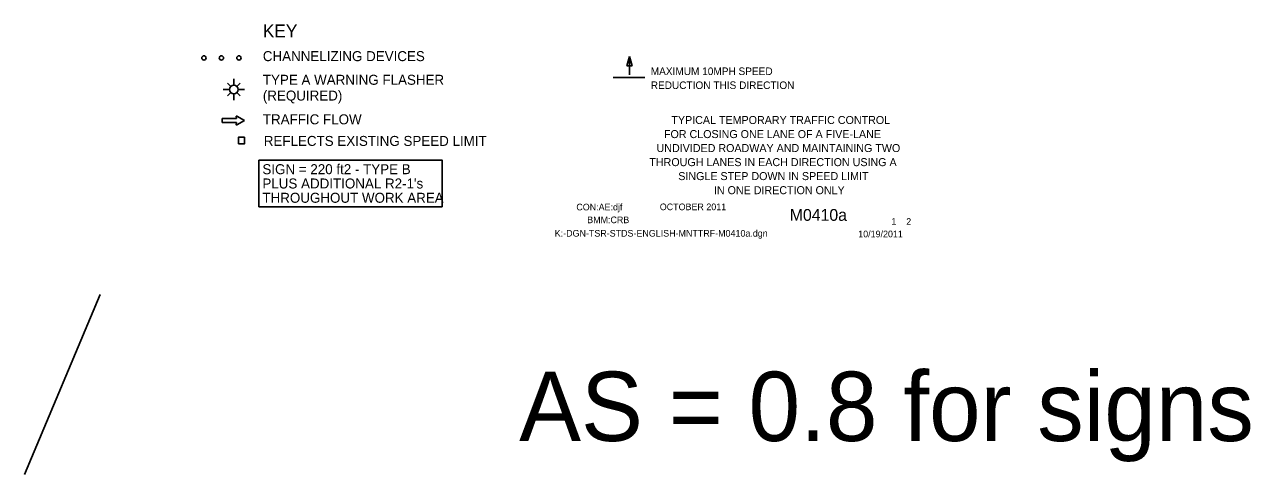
# Model space of a CAD drawing. Extents: x 16577 to 18475, y 5712 to 6919.
# Drawn here: x 16577 to 17718, y 5712 to 6131 of the extents above; entities that cross this region are included whole.
import ezdxf

# ---------------------------------------------------------------- set-up
doc = ezdxf.new("R2010")
doc.units = 0
for name, color, linetype in [('BORDER_SIGNAL_WO', 7, 'Continuous'), ('MT_SCRATCH_LEVEL_E', 7, 'Continuous'), ('TRAFFIC_SIGNS_PR', 7, 'Continuous'), ('TYPICAL_TEXT_DIMEN_EX', 7, 'Continuous'), ('TYPICAL_TEXT_DIMEN_PR', 7, 'Continuous')]:
    doc.layers.add(name, color=color, linetype=linetype)

msp = doc.modelspace()

# ---------------------------------------------------------------- linework, layer by layer
at = {"layer": 'MT_SCRATCH_LEVEL_E'}
for p, q in [((16774.2, 6045.4), (16774.5, 6043.6)), ((16774.2, 6045.4), (16774.5, 6043.6)), ((16782.1, 6041.7), (16774.9, 6045.8)), ((16782.1, 6041.7), (16774.9, 6045.8)), ((16774.5, 6043.6), (16761.2, 6043.6)), ((16761.2, 6043.6), (16761.2, 6039.8)), ((16774.5, 6043.6), (16761.2, 6043.6)), ((16761.2, 6043.6), (16761.2, 6039.8)), ((16761.2, 6039.8), (16774.5, 6039.8)), ((16761.2, 6039.8), (16774.5, 6039.8)), ((16774.5, 6039.8), (16774.2, 6038.1)), ((16774.5, 6039.8), (16774.2, 6038.1)), ((16774.9, 6037.6), (16782.1, 6041.7)), ((16774.9, 6037.6), (16782.1, 6041.7))]:
    msp.add_line(p, q, dxfattribs=at)
for centre, start, end in [((16774.7, 6045.4), 60.4248, 189.9638), ((16774.7, 6045.4), 60.4248, 189.9638), ((16774.7, 6038), 170.0362, 299.7731), ((16774.7, 6038), 170.0362, 299.7731)]:
    msp.add_arc(centre, 0.463, start, end, dxfattribs=at)
at = {"layer": 'TRAFFIC_SIGNS_PR'}
for p, q in [((16772.1, 6075), (16772.1, 6080.6)), ((16768.1, 6070.6), (16762.1, 6070.6)), ((16768.9, 6073.7), (16766.3, 6076.4)), ((16768.9, 6067.5), (16766.3, 6064.8)), ((16775.2, 6073.7), (16777.9, 6076.4)), ((16775.2, 6067.4), (16777.9, 6064.8)), ((16776, 6070.6), (16782.1, 6070.6)), ((16772.1, 6060.6), (16772.1, 6066.1))]:
    msp.add_line(p, q, dxfattribs=at)
msp.add_lwpolyline([(16776.3, 6019.9), (16781.9, 6019.9), (16781.9, 6026.1), (16776.3, 6026.1)], close=True, dxfattribs=at)
for centre, radius in [((16744.3, 6100), 2), ((16760.6, 6100), 2), ((16776.9, 6100), 2), ((16772.1, 6070.6), 3.94)]:
    msp.add_circle(centre, radius, dxfattribs=at)
at = {"layer": 'TYPICAL_TEXT_DIMEN_EX'}
msp.add_lwpolyline([(16795.4, 6004.9), (16965.8, 6004.9), (16965.8, 5961.5), (16795.4, 5961.5)], close=True, dxfattribs=at)
at = {"layer": 'TYPICAL_TEXT_DIMEN_PR'}
for p, q in [((17137.8, 6092.5), (17140.2, 6101.3)), ((17140.2, 6084.2), (17140.2, 6101.3)), ((17140.2, 6101.3), (17142.6, 6092.5)), ((17140.2, 6092.5), (17137.8, 6092.5)), ((17142.6, 6092.5), (17140.2, 6092.5)), ((17154.4, 6081.7), (17124.9, 6081.7)), ((16647.8, 5880), (16577.4, 5712.4))]:
    msp.add_line(p, q, dxfattribs=at)

# ---------------------------------------------------------------- texts
at = {"layer": 'BORDER_SIGNAL_WO'}
for s, height, p in [('TYPICAL TEMPORARY TRAFFIC CONTROL', 7.442, (17179.1, 6038.5)), ('FOR CLOSING ONE LANE OF A FIVE-LANE', 7.442, (17172.2, 6025.4)), ('UNDIVIDED ROADWAY AND MAINTAINING TWO', 7.442, (17165.3, 6012.4)), ('THROUGH LANES IN EACH DIRECTION USING A', 7.442, (17158.6, 5999.3)), ('SINGLE STEP DOWN IN SPEED LIMIT', 7.442, (17185.5, 5986.3)), (' IN ONE DIRECTION ONLY', 7.442, (17215.9, 5973.2)), ('CON:AE:djf', 6.2, (17090.7, 5958.1)), ('    OCTOBER 2011    ', 6.2, (17159.1, 5958.3)), ('BMM:CRB   ', 6.2, (17100.8, 5946.2)), ('    M0410a   ', 11, (17272.9, 5948.4)), (' 1    2 ', 6.2, (17381.4, 5944.7)), ('K:-DGN-TSR-STDS-ENGLISH-MNTTRF-M0410a.dgn        ', 6.2, (17070.6, 5933.7)), ('10/19/2011    ', 6.2, (17352.9, 5933.1)), ('AS = 0.8 for signs', 64.512, (17037.5, 5743.5))]:
    msp.add_text(s, height=height, dxfattribs=at).set_placement(p)
at = {"layer": 'TYPICAL_TEXT_DIMEN_EX'}
for s, height, p in [('KEY', 12, (16799.1, 6119.1)), ('CHANNELIZING DEVICES', 9.3, (16799.1, 6097)), ('TYPE A WARNING FLASHER', 9.3, (16799.1, 6075)), ('(REQUIRED)', 9.3, (16799.1, 6060.3)), ('TRAFFIC FLOW', 9.3, (16799.1, 6038.2)), ('REFLECTS EXISTING SPEED LIMIT', 9.3, (16800, 6018.1)), ('SIGN = 220 ft2 - TYPE B', 9.3, (16798.7, 5991.8)), ("PLUS ADDITIONAL R2-1's", 9.3, (16798.7, 5978.5)), ('THROUGHOUT WORK AREA', 9.3, (16798.7, 5965.2))]:
    msp.add_text(s, height=height, dxfattribs=at).set_placement(p)
at = {"layer": 'TYPICAL_TEXT_DIMEN_PR'}
for s, p in [('MAXIMUM 10MPH SPEED', (17159.9, 6084.1)), ('REDUCTION THIS DIRECTION', (17159.9, 6071.1))]:
    msp.add_text(s, height=7, dxfattribs=at).set_placement(p)

doc.saveas('drawing.dxf')
